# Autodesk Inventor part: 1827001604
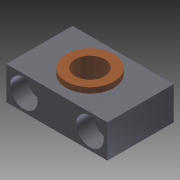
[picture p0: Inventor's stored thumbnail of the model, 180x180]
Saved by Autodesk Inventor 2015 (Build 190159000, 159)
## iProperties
Created: 2012-12
Part Number: 1827001604
Material: Generic
Document SubType Name: Modeling
Designer: Marci
Density: 1 g/cm^3
Appearance: Honed - Dark Gray
Translation Standard: STEP AP214IS
FileName: 1827001604
PreProcessor: PRO/ENGINEER BY PARAMETRIC TECHNOLOGY CORPORATION, 2006020
PostProcessor: Build: 160, Release: 2012 RTM - Date: Tue 03/01/2011
Sent Units: millimeter
Uncertainty: 0.007230485278019001
Author: Marci
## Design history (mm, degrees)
node "18270016041"
node "1827001604"
node "Base1"
